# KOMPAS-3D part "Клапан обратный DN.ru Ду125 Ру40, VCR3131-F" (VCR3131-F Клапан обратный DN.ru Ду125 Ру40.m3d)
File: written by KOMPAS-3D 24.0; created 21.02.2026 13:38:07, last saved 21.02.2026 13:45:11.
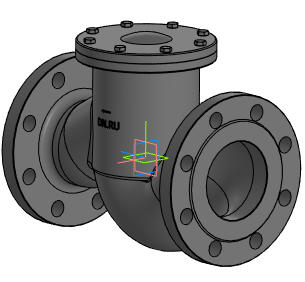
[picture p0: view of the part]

Document properties: Автор: R2D2; Полное имя файла: VCR3131-F Клапан обратный DN.ru Ду125 Ру40.cdw

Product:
- Part/product: Клапан обратный DN.ru Ду125 Ру40  | designation VCR3131-F
    Масса: 38
    Раздел спецификации: Прочие изделия
    Форматы листов документа: A2
    Примечание: D100-04045
    additional columns: D100-04045

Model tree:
1. Операция без истории:1

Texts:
  VCR3131-F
